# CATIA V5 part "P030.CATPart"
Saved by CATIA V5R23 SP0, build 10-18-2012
Part number: 05-LICP-T02-E-S05-P030
Definition: Bille Ø11
Description: Bille Ø11
Bounding box of the stored display mesh (mm): x -4.999 to 4.999, y -4.999 to 4.999, z -5 to 5
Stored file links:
  C:\wamp\www\COURS\CONCEPTION GMP1\TITRE 02-SEMESTRE 2\03-TP7-PRESSE MECANIQUE\eleve\P030.CATPart
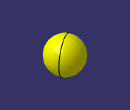
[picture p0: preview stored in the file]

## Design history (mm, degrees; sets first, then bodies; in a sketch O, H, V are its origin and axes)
Body1 (main body)
  Sketch1 on zx-plane, origin (0, 0, 0), H (-1, 0, 0), V (0, 0, 1)
    line L1 (0, 5) -> (0, -5)
    point P1 (0, 5)
    point P2 (0, -5)
    arc A1 centre (0, 0) radius 5 from (0, -5) to (0, 5) ccw
    length L1 = 10
    coincidence: P1 V
    vertical: L1 V
    symmetry: P2 P1 H
  Shaft1: profile Sketch1, axis Sketch1.V, angle 360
